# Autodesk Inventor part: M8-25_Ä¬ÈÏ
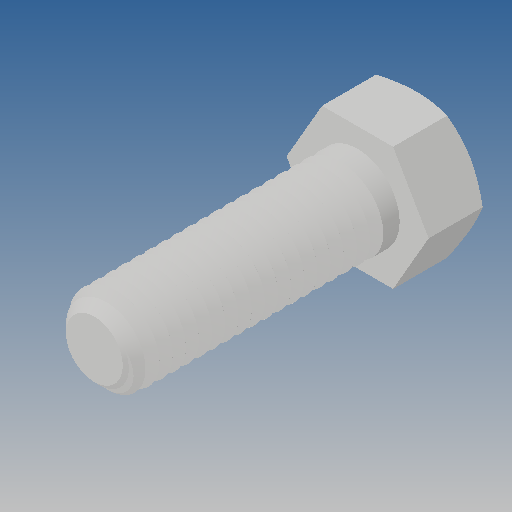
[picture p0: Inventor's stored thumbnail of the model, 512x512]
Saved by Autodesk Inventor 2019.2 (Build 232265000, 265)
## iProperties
Created: 2010-06
Part Number: M8-25_Ä¬ÈÏ
Material: Ogólny
Document SubType Name: Modeling
Designer: CADENGINEERING4
Density: 1 g/cm^3
Appearance: Domyślna
Author: CADENGINEERING4
Revision Number: ÈÎºÎ
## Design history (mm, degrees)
feature "NONE"
node "Bryła1"
